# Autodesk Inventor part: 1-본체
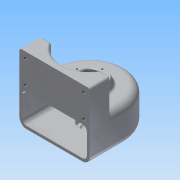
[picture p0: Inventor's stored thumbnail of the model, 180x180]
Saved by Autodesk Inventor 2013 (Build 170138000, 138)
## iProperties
Created: 2015-02
Part Number: 1-본체
Material: 알루미늄 6061
Document SubType Name: Modeling
Designer: Administrator
Density: 2.40731 g/cm^3
Mass: 511.093 g
Surface Area: 706.387 cm^2
Volume: 212.309 cm^3
Author: Administrator
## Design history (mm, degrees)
sketch "스케치1"
  geometry: L1 (-50, 0)-(-50, -50); L2 (-50, -50)-(50, -50); L3 (50, -50)-(50, 0); A1 r 50 centre (0, 0) between (50, 0) and (-50, 0); 1 further point
  constraints: 6 end point, 2 point on circle, 2 tangent, 1 centre point, 1 coincident, 1 parallel, 1 perpendicular, 1 vertical
  dimensions: "d0" = 50 radius of A1; "d2" = 50 distance of L3.end L2.end
extrude "돌출1" new body sketch "스케치1" distance "d3" = 50; taper "d4" = 0 deg
feature "쉘2" dims "d34" = 4
sketch "스케치2"
  geometry: C1 r 25 at (0, 0); A1 r 50 centre (0, 0) between (50, 0) and (-50, 0) reference
  constraints: 1 centre point, 1 coincident
  dimensions: "d5" = 50 diameter of C1
extrude "돌출2" join sketch "스케치2" distance "d7" = 10; taper "d8" = -20 deg
node "작업 평면1"
sketch "스케치5"
  geometry: C1 r 20 at (0, 0); 1 further point
  constraints: 1 centre point, 1 coincident
  dimensions: "d55" = 40 diameter of C1
extrude "돌출4" join sketch "스케치5" distance "d57" = 9; taper "d58" = 0 deg
hole "구멍5" diameter "d61" = 20; stored, may be unused: countersink angle "d65" = 90 deg, drill point angle "d67" = 0 deg; dims "d59" = 10, "d60" = 10, "d62" = 6, "d63" = 28, "d64" = 8, "d66" = 10
hole "구멍3" diameter "d37" = 20; stored, may be unused: countersink angle "d41" = 90 deg, drill point angle "d43" = 0 deg; dims "d35" = 10, "d36" = 10, "d38" = 6, "d39" = 28, "d40" = 10, "d42" = 14
fillet "모깎기1" dims "d53" = 10
node "작업 평면2"
sketch "스케치7"
  geometry: L1 (50, -50)-(50, 0) reference; L2 (40, 0)-(40, -50) reference; L3 (-40, -50)-(-40, 0) reference; L4 (-40, -50)-(40, -50) reference; L5 (-46, 0)-(-46, -50) reference; L6 (-50, 0)-(-50, -50) reference; L7 (34.641, -20)-(50, -20); L8 (34.641, -20)-(34.641, -50); L9 (50, -50)-(34.641, -50); L10 (50, -20)-(50, -50); L11 (-34.641, -20)-(-34.641, -50); L12 (-34.641, -20)-(-50, -20); L13 (-50, -20)-(-50, -50); L14 (-34.641, -50)-(-50, -50); L15 (-34.641, -50)-(34.641, -50); C1 r 25 at (0, 0) reference; A1 r 40 centre (0, 0) between (40, 0) and (-40, 0) reference; A2 r 50 centre (0, 0) between (50, 0) and (-50, 0) reference; A3 r 40 centre (0, 0) between (34.641, -20) and (-34.641, -20); 1 further point
  constraints: 18 end point, 5 collinear, 4 perpendicular, 4 point on line, 2 point on circle, 1 centre point, 1 coincident, 1 parallel
  dimensions: "d69" = 40 radius of A3; "d71" = 30 distance between parallel lines of L9 L7
extrude "돌출5" join sketch "스케치7" stored distance "d72" = 9; taper "d73" = 0 deg
sketch "스케치8"
  geometry: L1 (100, 10)-(100, 95) reference; L2 (0, 95)-(100, 95) reference; L3 (8.25, 53)-(91.75, 53); L4 (91.75, 53)-(91.75, 86); L5 (91.75, 86)-(8.25, 86); L6 (8.25, 86)-(8.25, 53); L7 (8.25, 53)-(91.75, 86); L8 (91.75, 53)-(8.25, 86); 7 further points
  constraints: 12 end point, 4 coincident, 2 midpoint, 2 parallel, 1 horizontal, 1 perpendicular
  dimensions: "d74" = 33 distance of L3.end L4.end; "d76" = 9 distance between parallel lines of L2 L5; "d77" = 83.5 distance of L4.end L5.end; "d78" = 8.25 distance between parallel lines of L4 L1
hole "구멍6" sketch "스케치8" at (91.75, 86), (91.75, 53), (8.25, 53), (8.25, 86) diameter "d79" = 5.134; stored, may be unused: countersink angle "d83" = 90 deg, drill point angle "d85" = 118 deg; dims "d80" = 10, "d81" = 28, "d82" = 8, "d84" = 13
fillet "모깎기2" dims "d86" = 6
sketch "스케치9"
  geometry: C1 r 14 at (0, 0) reference; C2 r 21.36 at (0, 0) reference; A1 r 18 centre (0, 0) between (0, 18) and (0, -18); 2 further points
  constraints: 4 point on circle, 2 horizontal alignment, 2 vertical alignment, 1 centre point, 1 coincident
  dimensions: "d87" = 36 diameter of A1
hole "구멍7" sketch "스케치9" at (0, 18), (0, -18), (18, 0), (-18, 0) diameter "d89" = 2.459; stored, may be unused: countersink angle "d93" = 90 deg, drill point angle "d95" = 118 deg; dims "d90" = 6, "d91" = 28, "d92" = 8, "d94" = 9
fillet "모깎기3" dims "d96" = 3
fillet "모깎기4" dims "d97" = 3
chamfer "모따기1" distance "d98" = 1; stored, may be unused: second distance "d99" = 2, angle "d100" = 45 deg
fillet "모깎기5" dims "d101" = 0.3
fillet "모깎기6" dims "d102" = 3
node "작업 평면3"
sketch "스케치10"
  geometry: L1 (40, 0)-(-40, 0) reference; 2 further points
  constraints: 1 vertical alignment, 1 other
  dimensions: "d103" = 25 distance from line of L1 point (0, 25)
feature "엠보싱1" sketch "스케치10" dims "d0" = 50, "d2" = 50, "d104" = 1, "d105" = 0
node "솔리드1"
node "투영된 루프1"
other parameters: "d54" = 9, "d68" = 95
